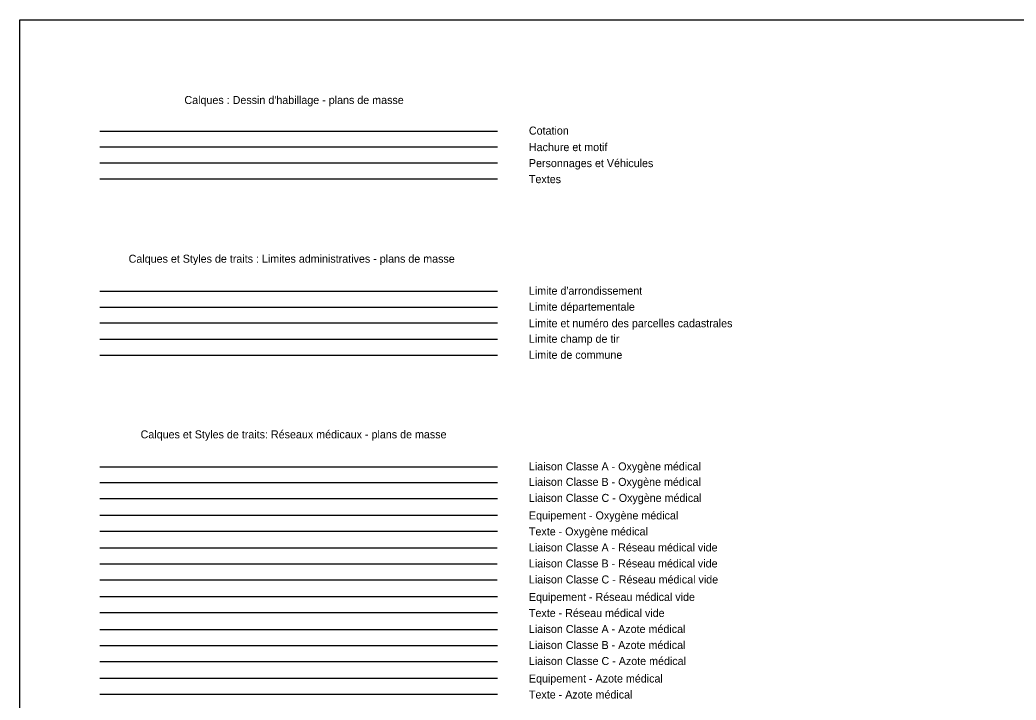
# Model space of a CAD drawing. Extents: x 703432 to 707394, y 7057985 to 7059523.
# Drawn here: x 707199.5 to 707261.7, y 7058602.1 to 7058644.6 of the extents above; entities that cross this region are included whole.
import ezdxf

# ---------------------------------------------------------------- set-up
doc = ezdxf.new("R2010")
doc.units = 0
for name, color, linetype in [('DH_CADRE -CARTOUCHE', 7, 'Continuous'), ('LIM_ADM ARRONDISSEMENT', 7, 'Continuous'), ('LIM_ADM DEPARTEMENT', 7, 'Continuous'), ('LIM_ADM_CADASTRE', 7, 'Continuous'), ('LIM_ADM_CHAMP TIR', 7, 'Continuous'), ('LIM_ADM_COMMUNE', 7, 'Continuous'), ('MASSE_DH_COTATION', 7, 'Continuous'), ('MASSE_DH_HACHURE-MOTIF', 7, 'Continuous'), ('MASSE_DH_PERSONNAGE_VEHICULES', 7, 'Continuous'), ('MASSE_DH_TEXTE', 7, 'Continuous'), ('R_MED_AZOTE_CANALISATION_CL_A', 7, 'Continuous'), ('R_MED_AZOTE_CANALISATION_CL_B', 7, 'Continuous'), ('R_MED_AZOTE_CANALISATION_CL_C', 7, 'Continuous'), ('R_MED_AZOTE_EQUIP', 7, 'Continuous'), ('R_MED_AZOTE_TEXTE', 7, 'Continuous'), ('R_MED_OXYGENE_CANALISATION_CL_A', 7, 'Continuous'), ('R_MED_OXYGENE_CANALISATION_CL_B', 7, 'Continuous'), ('R_MED_OXYGENE_CANALISATION_CL_C', 7, 'Continuous'), ('R_MED_OXYGENE_EQUIP', 7, 'Continuous'), ('R_MED_OXYGENE_TEXTE', 7, 'Continuous'), ('R_MED_VIDE_CANALISATION_CL_A', 7, 'Continuous'), ('R_MED_VIDE_CANALISATION_CL_B', 7, 'Continuous'), ('R_MED_VIDE_CANALISATION_CL_C', 7, 'Continuous'), ('R_MED_VIDE_EQUIP', 7, 'Continuous'), ('R_MED_VIDE_TEXTE', 7, 'Continuous')]:
    doc.layers.add(name, color=color, linetype=linetype)

msp = doc.modelspace()

# ---------------------------------------------------------------- linework, layer by layer
at = {"layer": 'DH_CADRE -CARTOUCHE'}
msp.add_lwpolyline([(707199.469, 7058644.551), (707324.469, 7058644.551), (707324.469, 7058419.551), (707199.469, 7058419.551)], close=True, dxfattribs=at)
at = {"layer": 'LIM_ADM ARRONDISSEMENT'}
msp.add_line((707204.469, 7058627.608), (707229.289, 7058627.608), dxfattribs=at)
at = {"layer": 'LIM_ADM DEPARTEMENT'}
msp.add_line((707204.469, 7058626.608), (707229.289, 7058626.608), dxfattribs=at)
at = {"layer": 'LIM_ADM_CADASTRE'}
msp.add_line((707229.289, 7058625.608), (707204.469, 7058625.608), dxfattribs=at)
at = {"layer": 'LIM_ADM_CHAMP TIR'}
msp.add_line((707204.469, 7058624.608), (707229.289, 7058624.608), dxfattribs=at)
at = {"layer": 'LIM_ADM_COMMUNE'}
msp.add_line((707204.469, 7058623.608), (707229.289, 7058623.608), dxfattribs=at)
at = {"layer": 'MASSE_DH_COTATION'}
msp.add_line((707204.469, 7058637.608), (707229.289, 7058637.608), dxfattribs=at)
at = {"layer": 'MASSE_DH_HACHURE-MOTIF'}
msp.add_line((707229.289, 7058636.608), (707204.469, 7058636.608), dxfattribs=at)
at = {"layer": 'MASSE_DH_PERSONNAGE_VEHICULES'}
msp.add_line((707229.289, 7058635.608), (707204.469, 7058635.608), dxfattribs=at)
at = {"layer": 'MASSE_DH_TEXTE'}
msp.add_line((707229.289, 7058634.608), (707204.469, 7058634.608), dxfattribs=at)
at = {"layer": 'R_MED_AZOTE_CANALISATION_CL_A'}
msp.add_line((707204.469, 7058606.484), (707229.284, 7058606.484), dxfattribs=at)
at = {"layer": 'R_MED_AZOTE_CANALISATION_CL_B'}
msp.add_line((707204.469, 7058605.484), (707229.284, 7058605.484), dxfattribs=at)
at = {"layer": 'R_MED_AZOTE_CANALISATION_CL_C'}
msp.add_line((707204.469, 7058604.484), (707229.284, 7058604.484), dxfattribs=at)
at = {"layer": 'R_MED_AZOTE_EQUIP'}
msp.add_line((707229.284, 7058603.422), (707204.469, 7058603.422), dxfattribs=at)
at = {"layer": 'R_MED_AZOTE_TEXTE'}
msp.add_line((707229.284, 7058602.422), (707204.469, 7058602.422), dxfattribs=at)
at = {"layer": 'R_MED_OXYGENE_CANALISATION_CL_A'}
msp.add_line((707204.469, 7058616.639), (707229.284, 7058616.639), dxfattribs=at)
at = {"layer": 'R_MED_OXYGENE_CANALISATION_CL_B'}
msp.add_line((707204.469, 7058615.67), (707229.284, 7058615.67), dxfattribs=at)
at = {"layer": 'R_MED_OXYGENE_CANALISATION_CL_C'}
msp.add_line((707204.469, 7058614.67), (707229.284, 7058614.67), dxfattribs=at)
at = {"layer": 'R_MED_OXYGENE_EQUIP'}
msp.add_line((707229.284, 7058613.608), (707204.469, 7058613.608), dxfattribs=at)
at = {"layer": 'R_MED_OXYGENE_TEXTE'}
msp.add_line((707229.284, 7058612.608), (707204.469, 7058612.608), dxfattribs=at)
at = {"layer": 'R_MED_VIDE_CANALISATION_CL_A'}
msp.add_line((707204.469, 7058611.577), (707229.269, 7058611.577), dxfattribs=at)
at = {"layer": 'R_MED_VIDE_CANALISATION_CL_B'}
msp.add_line((707204.469, 7058610.577), (707229.269, 7058610.577), dxfattribs=at)
at = {"layer": 'R_MED_VIDE_CANALISATION_CL_C'}
msp.add_line((707204.469, 7058609.577), (707229.269, 7058609.577), dxfattribs=at)
at = {"layer": 'R_MED_VIDE_EQUIP'}
msp.add_line((707229.284, 7058608.515), (707204.469, 7058608.515), dxfattribs=at)
at = {"layer": 'R_MED_VIDE_TEXTE'}
msp.add_line((707229.284, 7058607.515), (707204.469, 7058607.515), dxfattribs=at)

# ---------------------------------------------------------------- texts
at = {"layer": 'DH_CADRE -CARTOUCHE'}
for s, p in [("Calques : Dessin d'habillage - plans de masse", (707209.742, 7058639.301)), ('Calques et Styles de traits : Limites administratives - plans de masse', (707206.258, 7058629.389)), (' Calques et Styles de traits: Réseaux médicaux - plans de masse', (707206.82, 7058618.42))]:
    msp.add_text(s, height=0.5, dxfattribs=at).set_placement(p)
at = {"layer": 'LIM_ADM ARRONDISSEMENT'}
msp.add_text("Limite d'arrondissement", height=0.5, dxfattribs=at).set_placement((707231.252, 7058627.389))
at = {"layer": 'LIM_ADM DEPARTEMENT'}
msp.add_text('Limite départementale', height=0.5, dxfattribs=at).set_placement((707231.252, 7058626.389))
at = {"layer": 'LIM_ADM_CADASTRE'}
msp.add_text('Limite et numéro des parcelles cadastrales', height=0.5, dxfattribs=at).set_placement((707231.252, 7058625.358))
at = {"layer": 'LIM_ADM_CHAMP TIR'}
msp.add_text('Limite champ de tir', height=0.5, dxfattribs=at).set_placement((707231.252, 7058624.389))
at = {"layer": 'LIM_ADM_COMMUNE'}
msp.add_text('Limite de commune', height=0.5, dxfattribs=at).set_placement((707231.252, 7058623.389))
at = {"layer": 'MASSE_DH_COTATION'}
msp.add_text('Cotation', height=0.5, dxfattribs=at).set_placement((707231.252, 7058637.389))
at = {"layer": 'MASSE_DH_HACHURE-MOTIF'}
msp.add_text('Hachure et motif', height=0.5, dxfattribs=at).set_placement((707231.252, 7058636.358))
at = {"layer": 'MASSE_DH_PERSONNAGE_VEHICULES'}
msp.add_text('Personnages et Véhicules', height=0.5, dxfattribs=at).set_placement((707231.252, 7058635.358))
at = {"layer": 'MASSE_DH_TEXTE'}
msp.add_text('Textes', height=0.5, dxfattribs=at).set_placement((707231.252, 7058634.358))
at = {"layer": 'R_MED_AZOTE_CANALISATION_CL_A'}
msp.add_text('Liaison Classe A - Azote médical', height=0.5, dxfattribs=at).set_placement((707231.252, 7058606.265))
at = {"layer": 'R_MED_AZOTE_CANALISATION_CL_B'}
msp.add_text('Liaison Classe B - Azote médical', height=0.5, dxfattribs=at).set_placement((707231.252, 7058605.265))
at = {"layer": 'R_MED_AZOTE_CANALISATION_CL_C'}
msp.add_text('Liaison Classe C - Azote médical', height=0.5, dxfattribs=at).set_placement((707231.252, 7058604.265))
at = {"layer": 'R_MED_AZOTE_EQUIP'}
msp.add_text('Equipement - Azote médical', height=0.5, dxfattribs=at).set_placement((707231.252, 7058603.172))
at = {"layer": 'R_MED_AZOTE_TEXTE'}
msp.add_text('Texte - Azote médical', height=0.5, dxfattribs=at).set_placement((707231.252, 7058602.172))
at = {"layer": 'R_MED_OXYGENE_CANALISATION_CL_A'}
msp.add_text('Liaison Classe A - Oxygène médical', height=0.5, dxfattribs=at).set_placement((707231.252, 7058616.42))
at = {"layer": 'R_MED_OXYGENE_CANALISATION_CL_B'}
msp.add_text('Liaison Classe B - Oxygène médical', height=0.5, dxfattribs=at).set_placement((707231.252, 7058615.451))
at = {"layer": 'R_MED_OXYGENE_CANALISATION_CL_C'}
msp.add_text('Liaison Classe C - Oxygène médical', height=0.5, dxfattribs=at).set_placement((707231.252, 7058614.451))
at = {"layer": 'R_MED_OXYGENE_EQUIP'}
msp.add_text('Equipement - Oxygène médical', height=0.5, dxfattribs=at).set_placement((707231.252, 7058613.358))
at = {"layer": 'R_MED_OXYGENE_TEXTE'}
msp.add_text('Texte - Oxygène médical', height=0.5, dxfattribs=at).set_placement((707231.252, 7058612.358))
at = {"layer": 'R_MED_VIDE_CANALISATION_CL_A'}
msp.add_text('Liaison Classe A - Réseau médical vide', height=0.5, dxfattribs=at).set_placement((707231.252, 7058611.358))
at = {"layer": 'R_MED_VIDE_CANALISATION_CL_B'}
msp.add_text('Liaison Classe B - Réseau médical vide', height=0.5, dxfattribs=at).set_placement((707231.252, 7058610.358))
at = {"layer": 'R_MED_VIDE_CANALISATION_CL_C'}
msp.add_text('Liaison Classe C - Réseau médical vide', height=0.5, dxfattribs=at).set_placement((707231.252, 7058609.358))
at = {"layer": 'R_MED_VIDE_EQUIP'}
msp.add_text('Equipement - Réseau médical vide', height=0.5, dxfattribs=at).set_placement((707231.252, 7058608.265))
at = {"layer": 'R_MED_VIDE_TEXTE'}
msp.add_text('Texte - Réseau médical vide', height=0.5, dxfattribs=at).set_placement((707231.252, 7058607.265))

doc.saveas('drawing.dxf')
